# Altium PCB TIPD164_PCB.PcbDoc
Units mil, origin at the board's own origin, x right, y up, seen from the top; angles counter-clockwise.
Board outline 3000 x 3000 mil, 4 copper layers (Top Layer, Mid-Layer 1, Mid-Layer 2, Bottom Layer); 85 components, 50 nets, 262 pads, 186 vias.
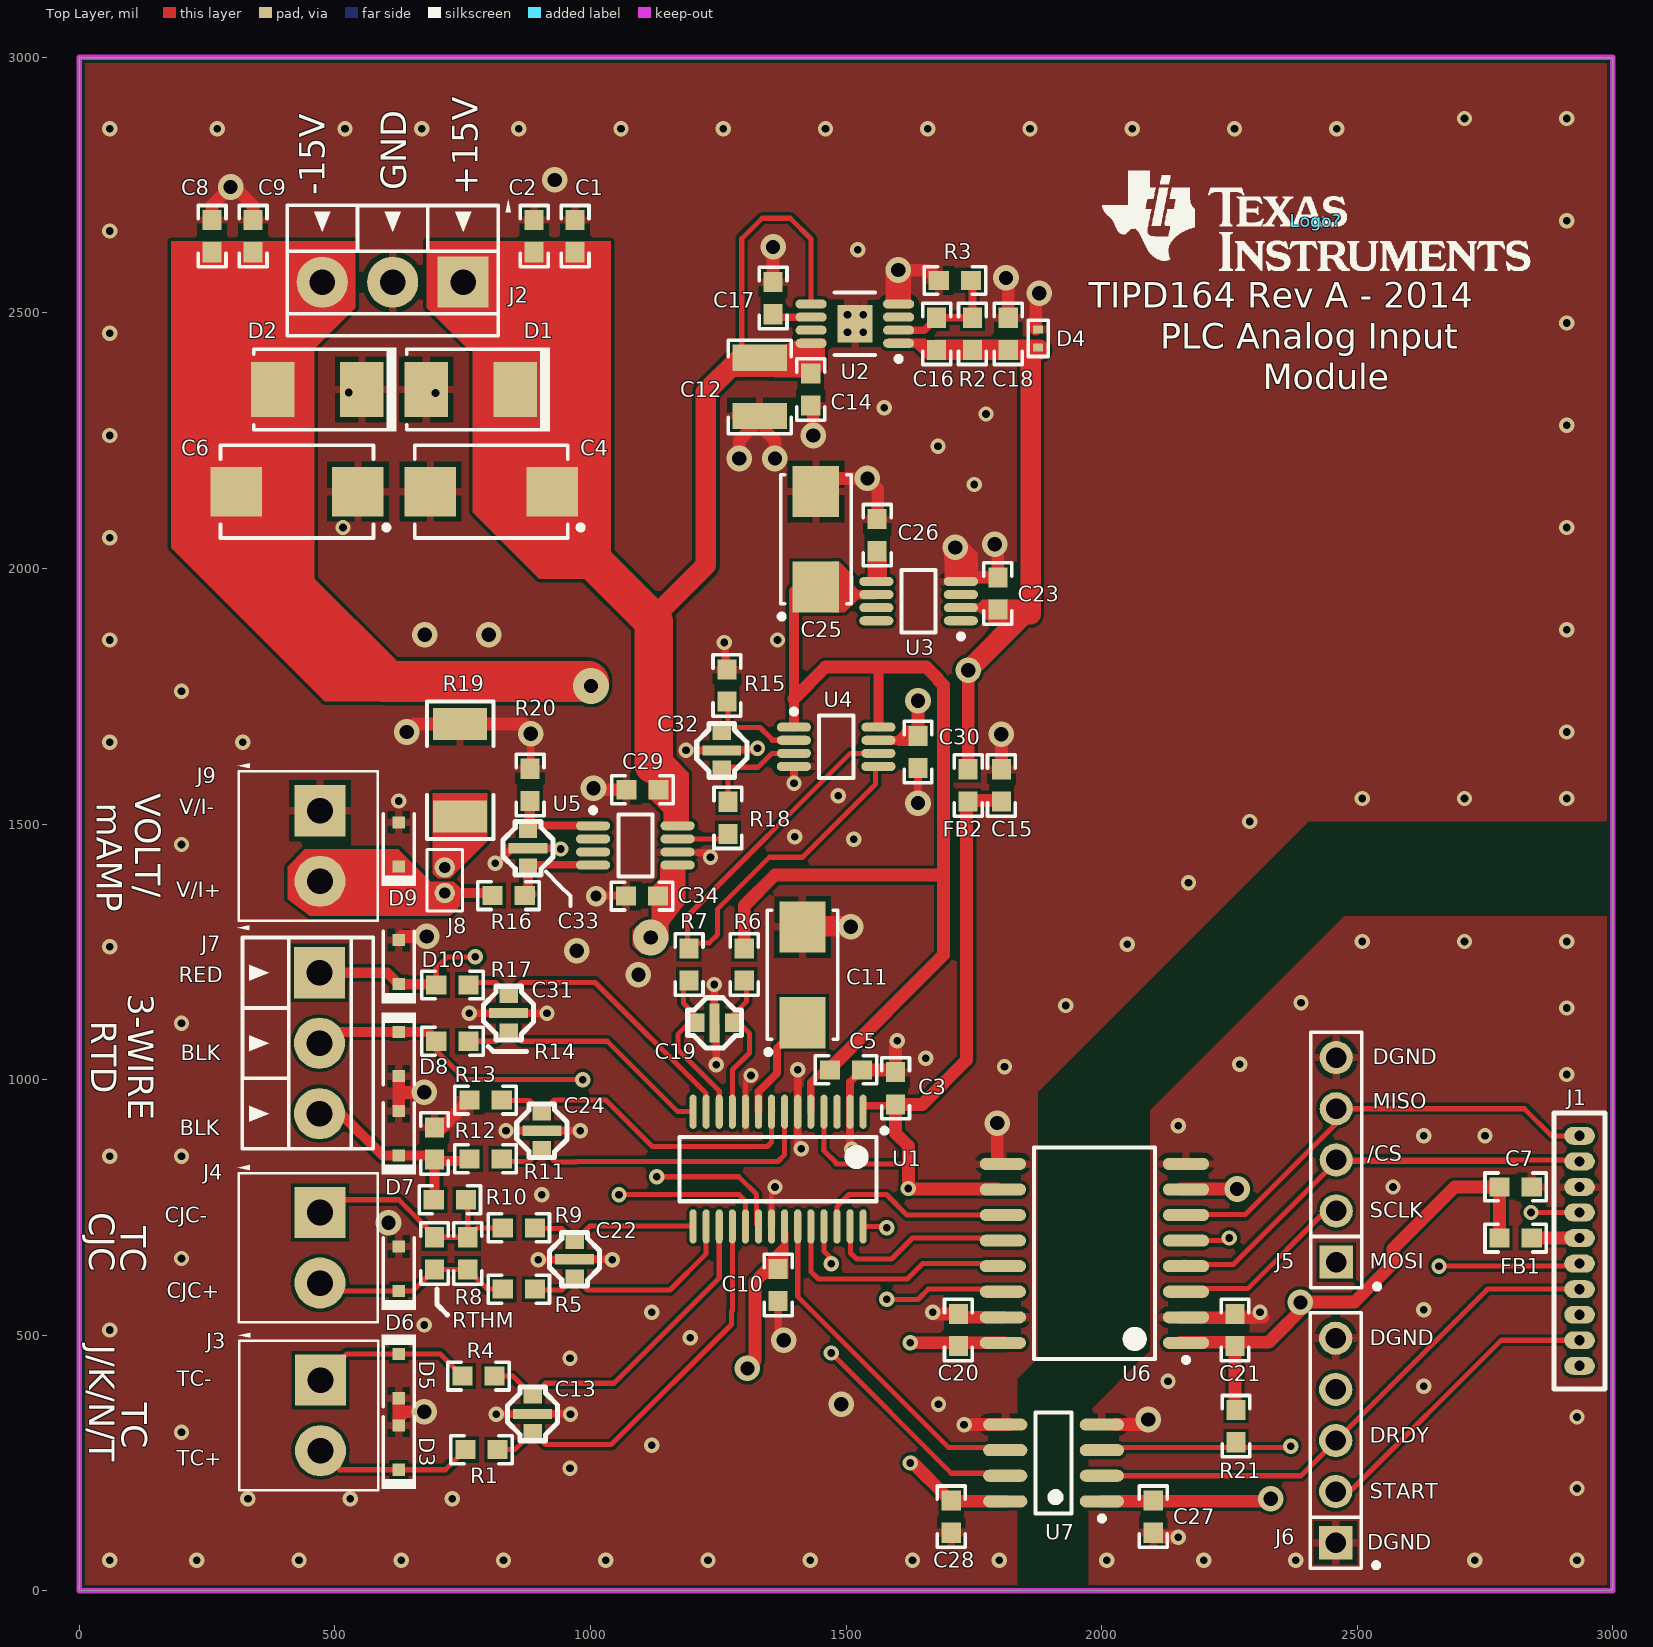
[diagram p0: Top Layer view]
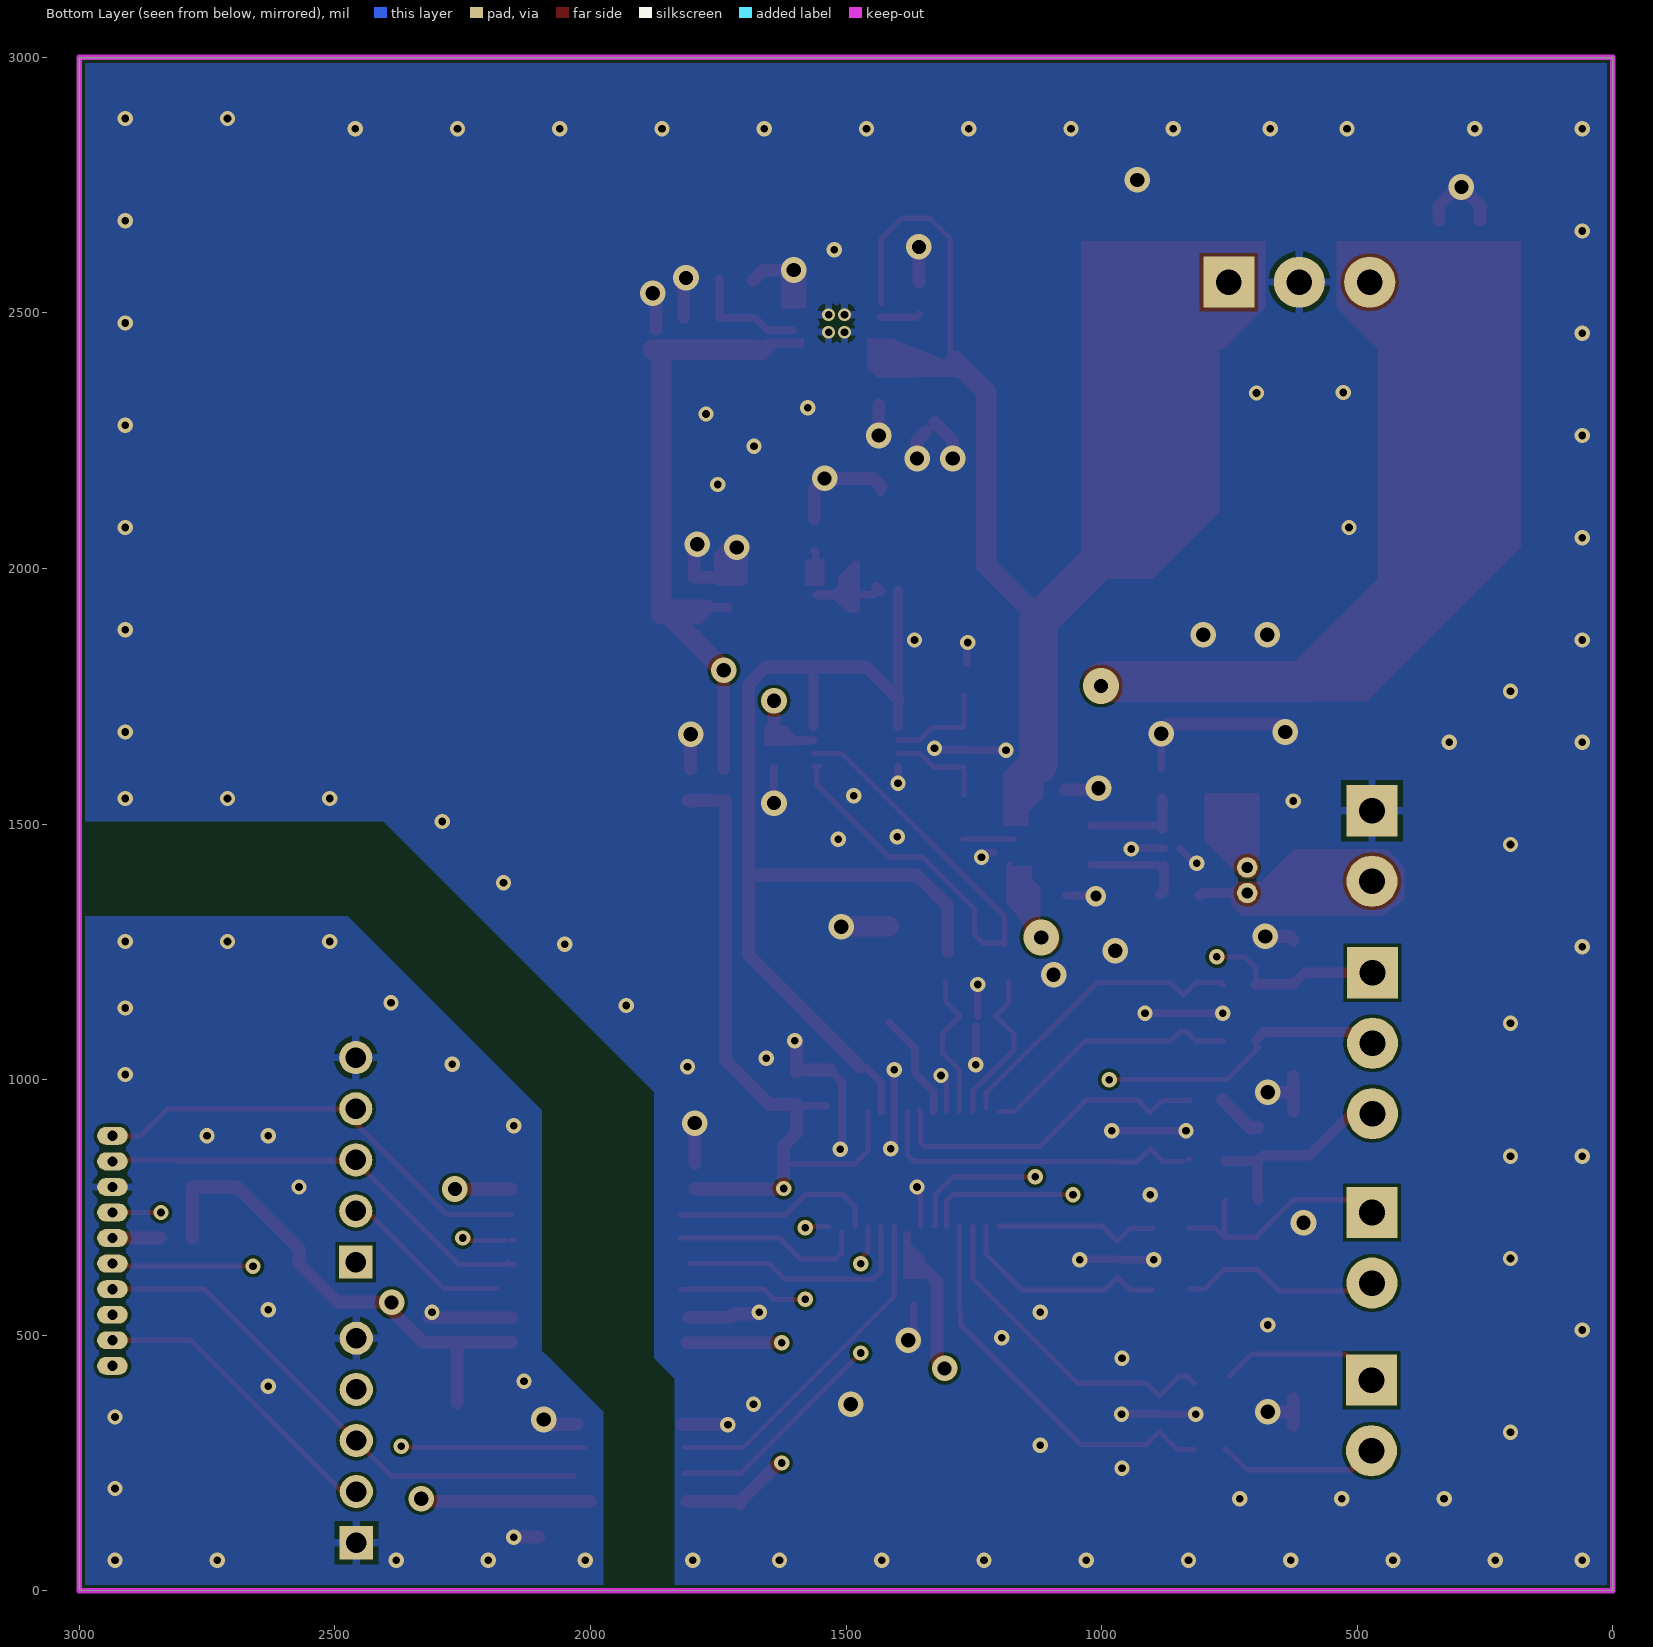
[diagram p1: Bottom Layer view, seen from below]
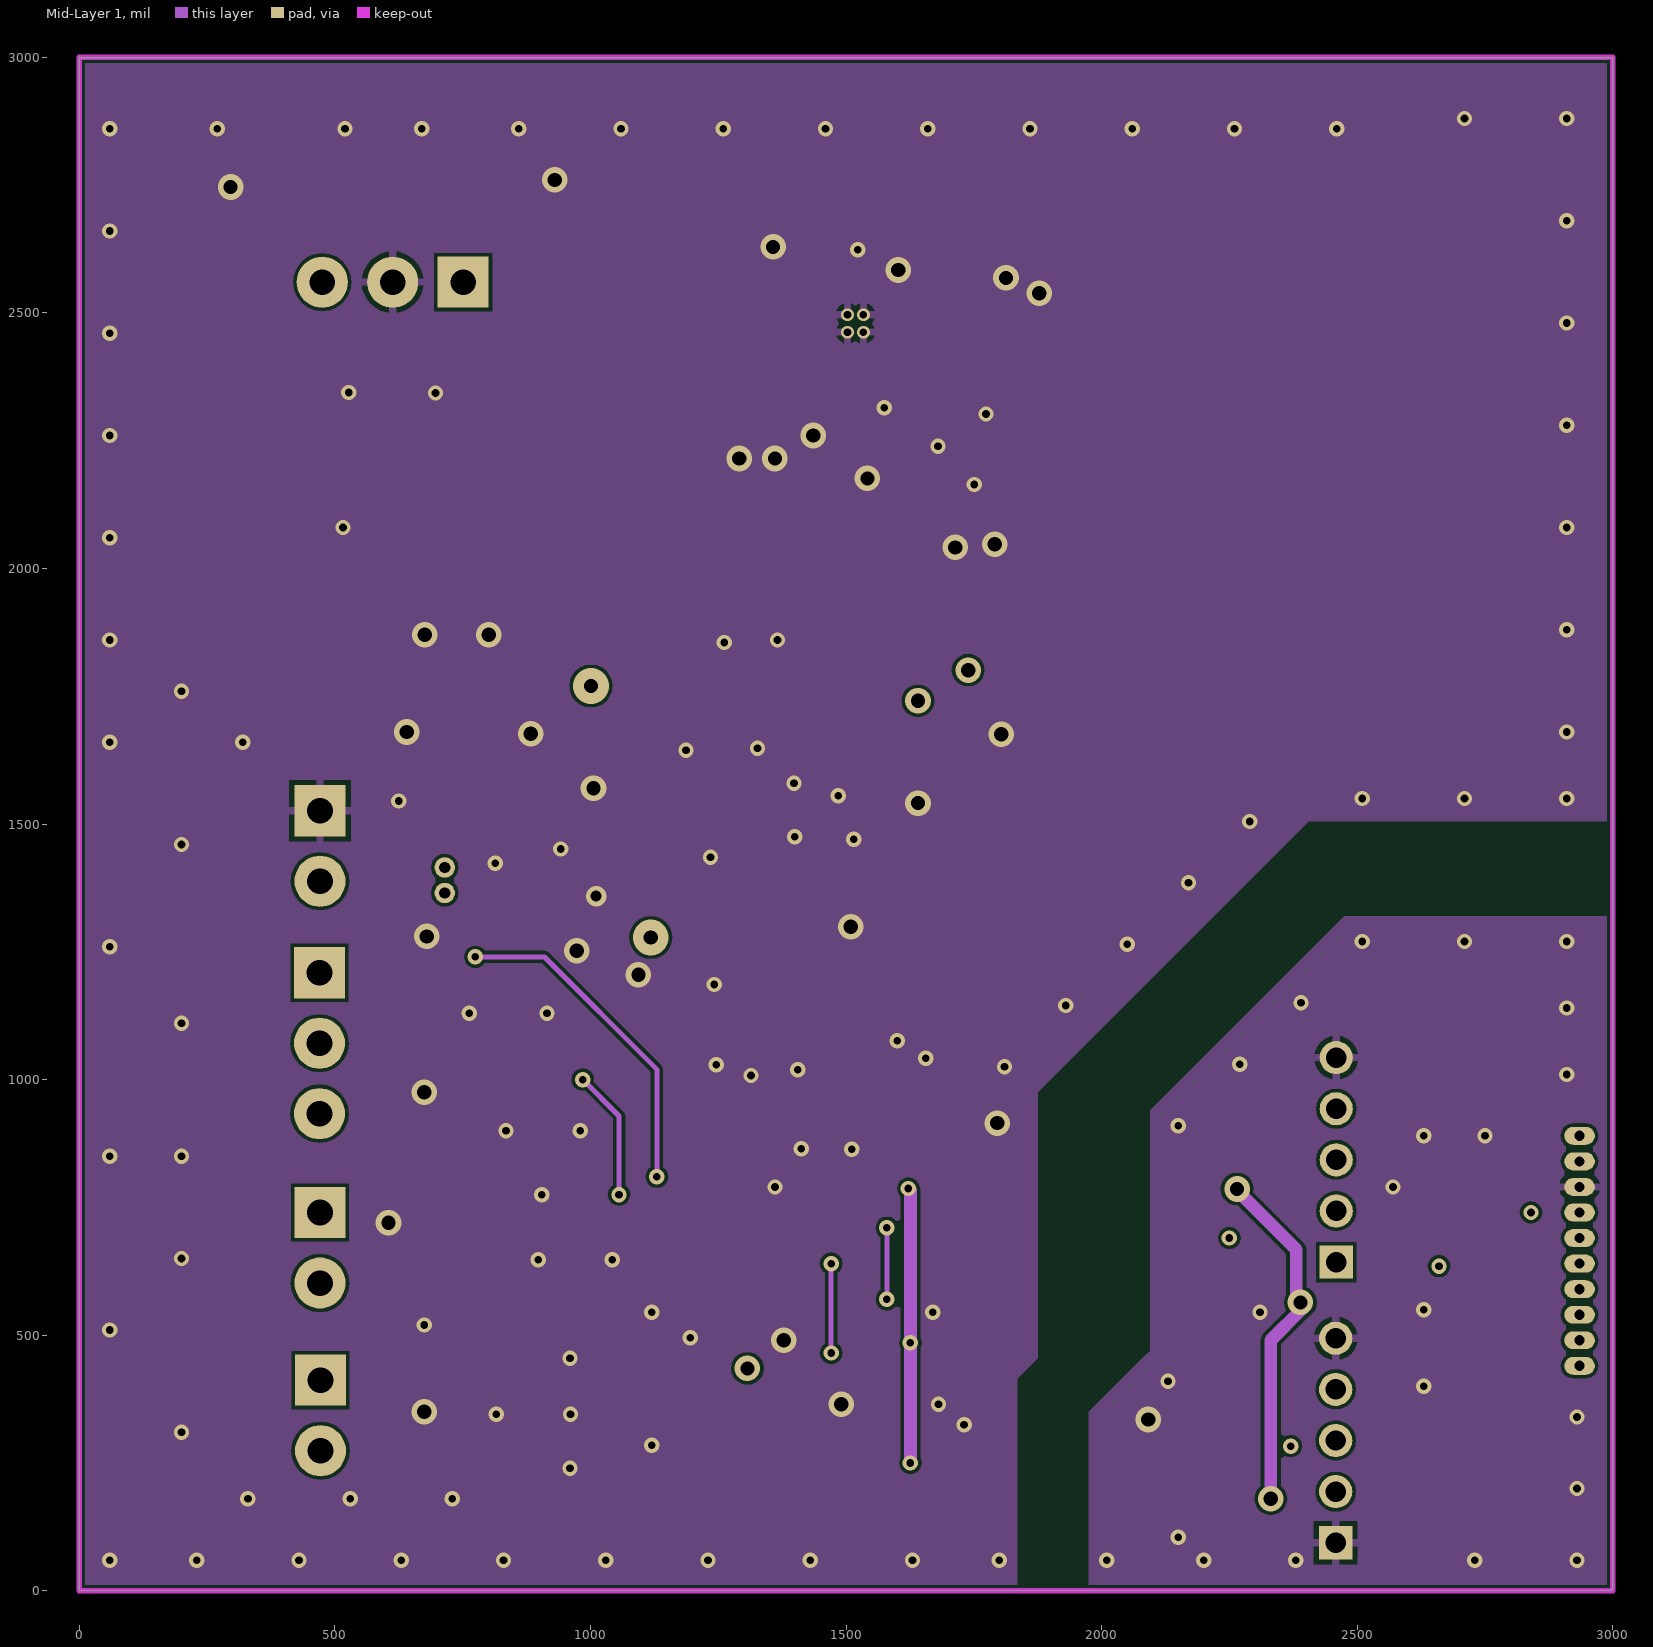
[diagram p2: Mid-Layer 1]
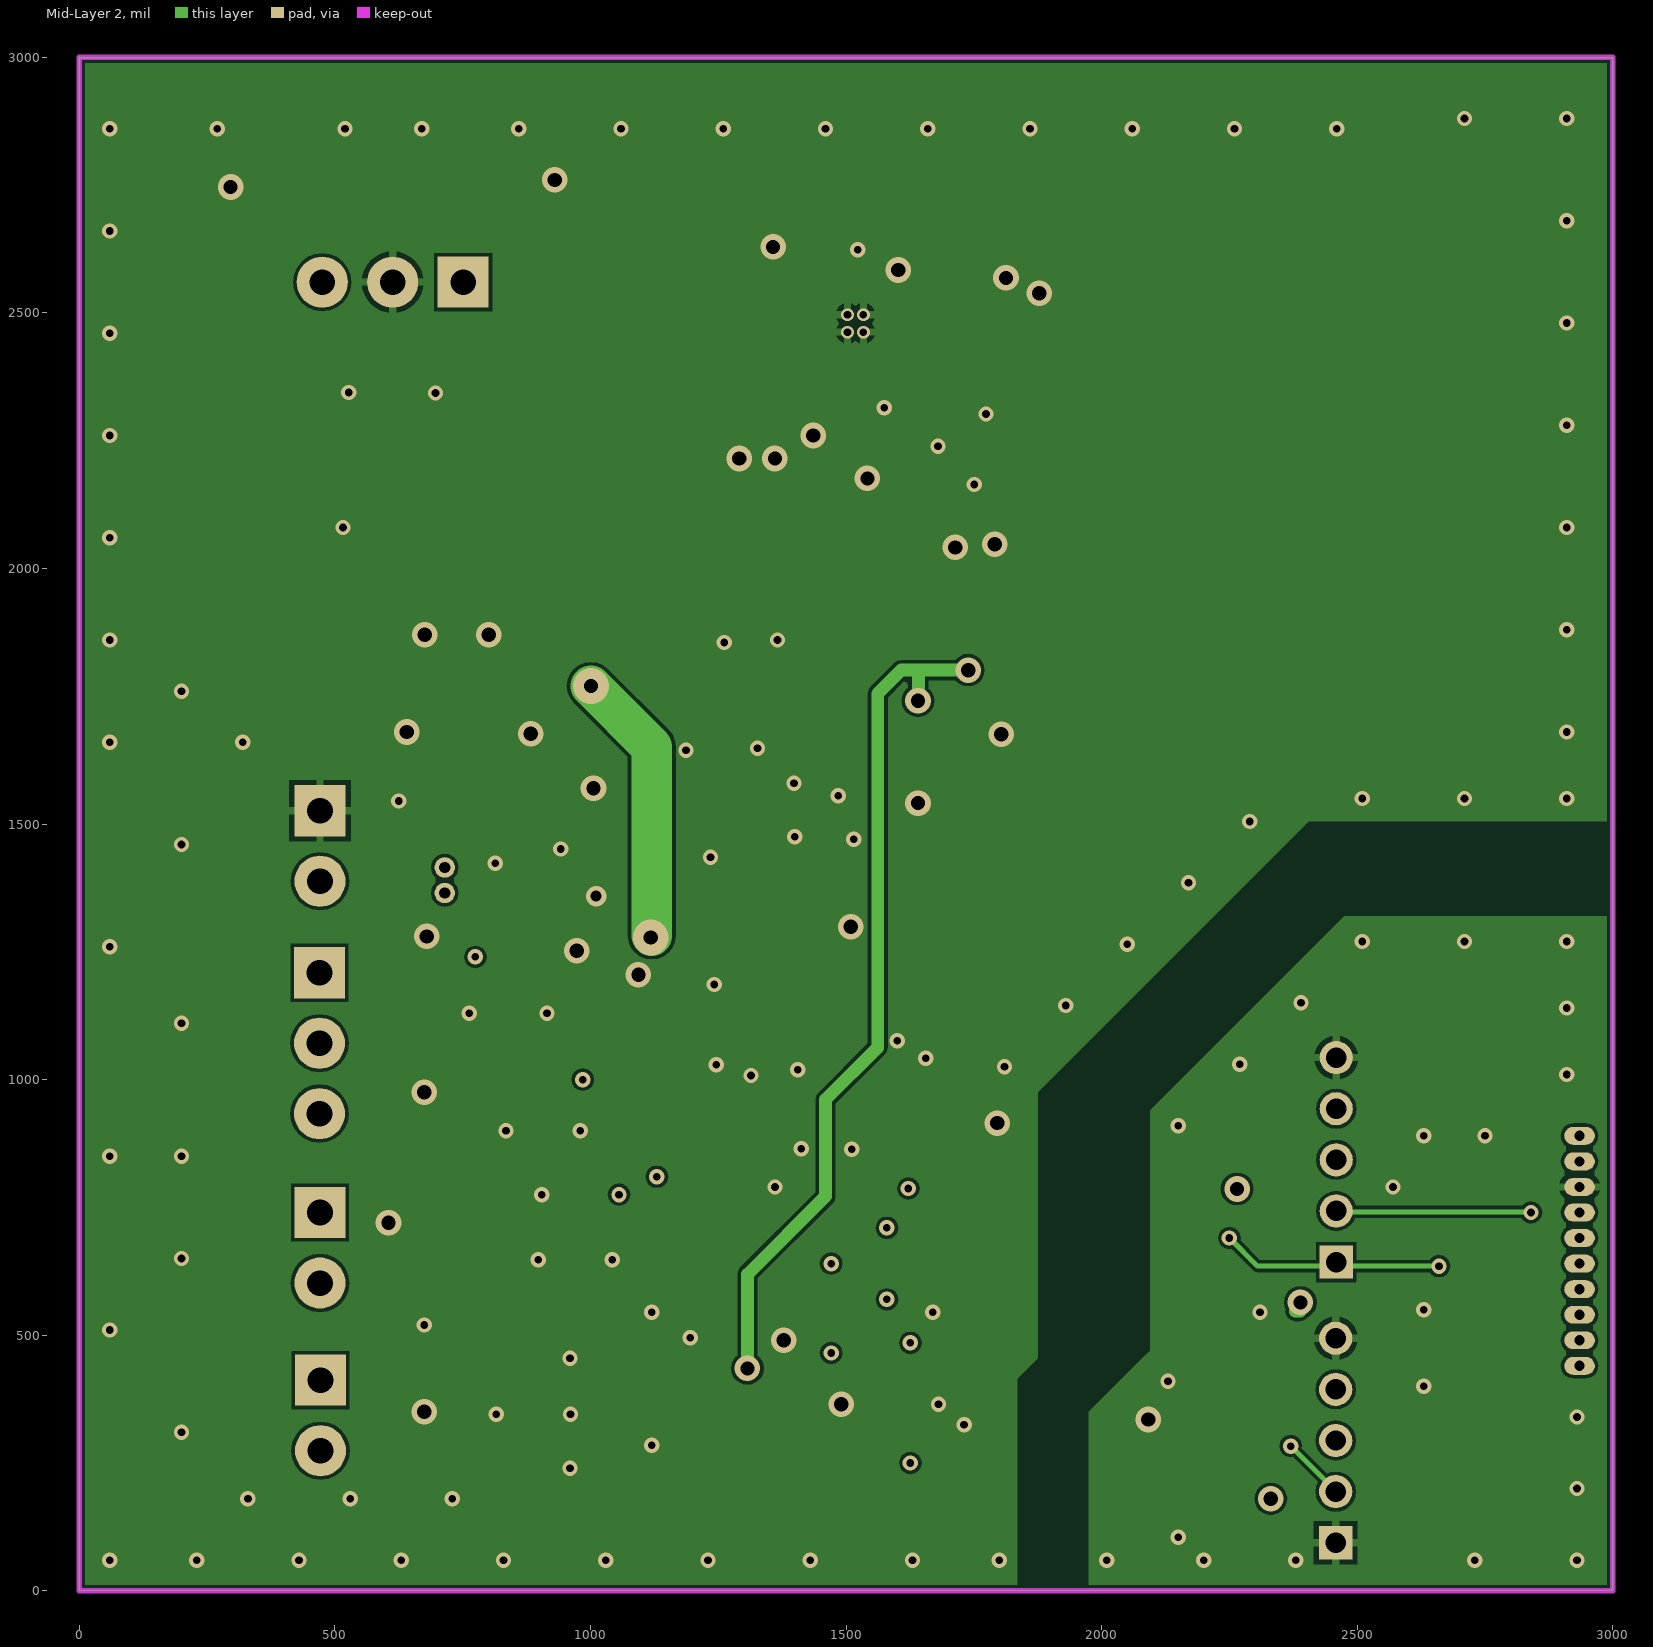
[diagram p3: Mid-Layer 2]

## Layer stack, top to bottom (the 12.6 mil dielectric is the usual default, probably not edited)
Top Layer: signal copper 1.4
Dielectric: core 12.6, FR-4, Dk 4.8
Mid-Layer 1: signal copper 1.4
Dielectric: prepreg 12.6, FR-4, Dk 4.8
Mid-Layer 2: signal copper 1.4
Dielectric: core 12.6, FR-4, Dk 4.8
Bottom Layer: signal copper 1.4

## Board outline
2997,1 3000,4 3000,2999 1,2999 0,3000 0,0

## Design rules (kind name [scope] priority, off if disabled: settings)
Clearance [All] p1: gap=6.5
HoleToHoleClearance [All] p1: gap=0 allowstackedmicrovias=TRUE
MinimumSolderMaskSliver [All] p1: minsoldermaskwidth=0
PolygonConnect PolygonConnect_1 [(InComponentClass('All Components'))] p1: connectstyle=Relief reliefconductorwidth=15 reliefentries=4 polygonreliefangle="90 Angle" airgapwidth=10
PolygonConnect [All] p2: connectstyle=Direct reliefconductorwidth=20 reliefentries=4 polygonreliefangle="90 Angle" airgapwidth=10
RoutingVias [All] p1: holewidth=15 width=30 viastyle="Through Hole" minholewidth=15 minwidth=30 maxholewidth=28 maxwidth=50
SilkToSilkClearance [All] p1 off: silktosilkclearance=10
SilkscreenOverComponentPads [All] p1 off: minsilkscreentomaskgap=10
SolderMaskExpansion [All] p1: expansion=4
Width [All] p1: maxlimit=200 minlimit=10 preferedwidth=10
24 further rules are at their usual default settings.

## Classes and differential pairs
component class Header: J5 J6
component class Logo: Logo?

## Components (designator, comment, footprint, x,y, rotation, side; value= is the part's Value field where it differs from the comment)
C1 "GRM188R71H104KA93D" 0603 970,2650 r270 top
C2 "06035A101JAT2A" 0603 890,2650 r90 top
C3 "GRM188R71H104KA93D" 0603 1597,983 r90 top
C4 "293D106X9050E2TE3" 7343-43 806,2150 r180 top
C5 "GRM188R71H104KA93D" 0603 1500,1019 r0 top
C6 "293D106X9050E2TE3" 7343-43 426,2150 r180 top
C7 "GRM188R71H104KA93D" 0603 2810,790 r0 top
C8 "GRM188R71H104KA93D" 0603 260,2650 r90 top
C9 "06035A101JAT2A" 0603 340,2650 r270 top
C10 "GRM188R71H104KA93D" 0603 1367.2,598 r270 top
C11 "293D226X9010C2TE3" 6032-28 1415,1205 r90 top
C12 "C3225X7R1E106M" 1210 1331,2355 r270 top
C13 "0.047uF X2Y" X2Y_0603 887,346 r90 top
C14 "GRM188R71H104KA93D" 0603 1431,2350 r270 top
C15 "GRM188R71H104KA93D" 0603 1804,1575.5 r90 top
C16 "C0603C103J5RACTU" 0603 1677.37,2458.81 r90 top
C17 "C0603C103J5RACTU" 0603 1357.37,2528.81 r90 top
C18 "GRM188R71H104KA93D" 0603 1817.37,2458.81 r90 top
C19 "0.047uF X2Y" X2Y_0603 1243,1111 r0 top
C20 "GRM188R71H104KA93D" 0603 1720,510 r90 top
C21 "GRM188R71H104KA93D" 0603 2261,510 r90 top
C22 "0.047uF X2Y" X2Y_0603 969,648.5 r90 top
C23 "GRM188R71H104KA93D" 0603 1797,1951 r90 top
C24 "0.047uF X2Y" X2Y_0603 905,900 r90 top
C25 "293D226X9010C2TE3" 6032-28 1441,2057 r90 top
C26 "GRM188R71H104KA93D" 0603 1561,2065 r90 top
C27 "GRM188R71H104KA93D" 0603 2101,145 r270 top
C28 "GRM188R71H104KA93D" 0603 1706,145 r270 top
C29 "GRM188R71H104KA93D" 0603 1102,1567 r180 top
C30 "GRM188R71H104KA93D" 0603 1640.8,1641 r270 top
C31 "0.047uF X2Y" X2Y_0603 840,1130 r90 top
C32 "0.047uF X2Y" X2Y_0603 1257,1644 r270 top
C33 "0.047uF X2Y" X2Y_0603 878,1452.5 r90 top
C34 "GRM188R71H104KA93D" 0603 1101,1359 r180 top
D1 "SMBJ15A-13-F" SMB 766,2350 r180 top
D2 "SMBJ15A-13-F" SMB 466,2350 r180 top
D3 "DESD5V0S1BA" SOD-323 625,280 r90 top
D4 "ESD9L5.0ST5G" SOD-923 1876,2450 r270 top
D5 "DESD5V0S1BA" SOD-323 625,420 r270 top
D6 "DESD5V0S1BA" SOD-323 625,630 r90 top
D7 "DESD5V0S1BA" SOD-323 625,895 r90 top
D8 "DESD5V0S1BA" SOD-323 625,1050 r270 top
D9 "CDSOD323-T15SC" sod-323 625,1460 r90 top
D10 "DESD5V0S1BA" SOD-323 625,1230 r90 top
FB1 "BLM18HG601SN1D" 0603 2810,690 r180 top
FB2 "BLM18HG601SN1D" 0603 1739,1575.5 r270 top
J1 "851-43-050-20-001000" 851-43-010-20-001000 2935,665 r180 top
J2 "ED555/3DS" TERM_BLK_ED555-3DS 751,2560 r180 top
J3 "ED555/2DS" TERM_BLK_ED555-2DS 472,412 r270 top
J4 "ED555/2DS" TERM_BLK_ED555-2DS 471,740 r270 top
J5 "TSW-105-07-G-S" TSW-105-07-G-S 2459,843 r90 top
J6 "TSW-105-07-G-S" TSW-105-07-G-S 2458,294 r90 top
J7 "ED555/3DS" TERM_BLK_ED555-3DS 470,1209 r270 top
J8 "TMS-102-02-G-S" "50mil Header" 715,1365 r90 top
J9 "ED555/2DS" TERM_BLK_ED555-2DS 471,1526 r270 top
Logo? "Texas Instruments" TI_Stacked_Overlay_Small 2420,2680 r0 top
R1 "CRCW0603249RFKEA" 0603 787,276 r180 top
R2 "ERA-3AEB1653V" 0603 1747.37,2458.81 r90 top
R3 "RG1608P-5112-B-T5" 0603 1713,2563.19 r0 top
R4 "CRCW0603249RFKEA" 0603 781,420 r180 top
R5 "RG1608P-2490-B-T5" 0603 860,590 r180 top
R6 "CRCW0603249RFKEA" 0603 1301,1225 r270 top
R7 "CRCW0603249RFKEA" 0603 1193,1225 r270 top
R8 "RG1608P-202-B-T5" 0603 760,660 r270 top
R9 "RG1608P-2490-B-T5" 0603 860,710 r180 top
R10 "CRCW06030000Z0EA" 0603 725,765 r0 top
R11 "CRCW0603249RFKEA" 0603 795,845 r180 top
R12 "RG2012V-822-P-T1" 0603 695,875 r90 top
R13 "CRCW0603249RFKEA" 0603 795,960 r180 top
R14 "CRCW0603249RFKEA" 0603 730,1075 r180 top
R15 "MCT06030C1008FP500" 0603 1267,1771 r270 top
R16 "CRCW0603249RFKEA" 0603 840,1360 r0 top
R17 "CRCW0603249RFKEA" 0603 730,1185 r180 top
R18 "MCT06030C1008FP500" 0603 1269,1512 r90 top
R19 "RT2010BKC07249RL" 2010 745,1605 r270 top
R20 "CRCW0603249RFKEA" 0603 882,1576.5 r270 top
R21 "CRCW0603100KFKEA" 0603 2263,322 r90 top
RTHM "NTCS0603E3473FHT" 0603 695,660 r270 top
U1 "ADS1248" MTC28_N 1367.2,825 r270 top
U2 "TPS7A4901" MUY08A_N 1517.37,2478.81 r180 top
U3 "REF5025" MUA08A_N 1642,1936 r180 top
U4 "INA159" MUA08A_N 1480.8,1651 r0 top
U5 "INA826" MUA08A_N 1088,1458 r0 top
U6 "ISO7641FCDW" M16B_N 1986,660 r180 top
U7 "ISO7221BD" D0008A_N 1906,250 r180 top

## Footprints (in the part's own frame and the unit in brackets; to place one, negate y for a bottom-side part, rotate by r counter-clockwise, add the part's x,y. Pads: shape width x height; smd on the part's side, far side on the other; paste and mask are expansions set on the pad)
"50mil Header" [mil]
  round 40 hole 22: 1(0,0) 2(50,0)
  silkscreen extent -35,-35 85,35
0603 [mm] "0603 from SM-752 data"
  rect 1x0.95 smd: 1(-0.8,0) 2(0.8,0)
  silkscreen extent -1.52,-0.69 1.52,0.69, body extent -0.87,-0.47 0.87,0.47, height 0.85
851-43-010-20-001000 [mil] "Female 10 Pin connector for SM-USB-DIG"
  oval 60x35 hole 20: 1(0,225) 2(0,175) 3(0,125) 4(0,75) 5(0,25) 6(0,-25) 7(0,-75) 8(0,-125) 9(0,-175) 10(0,-225)
  silkscreen extent -50,-270 50,270, body extent -210,-257 8,257, height 87
1210 [mm] "1210 from SM-752 data"
  rect 1.3x2.7 smd: 1(-1.45,0) 2(1.45,0)
  silkscreen extent -2.32,-1.57 2.32,1.57, body extent -1.7,-1.35 1.7,1.35, height 1.35
2010 [mm] "Chip Capacitor, Body 5.08x2.54mm, IPC Medium Density"
  rect 1.6x2.7 smd: 1(-2.3,0) 2(2.3,0)
  silkscreen extent -3.42,-1.65 3.42,1.65, body extent -2.73,-1.45 2.73,1.45, height 1.66
6032-28 [mm] "Medium Density IPC based on Vishay Sprague 293D datasheet."
  rect 2.55x2.3 smd: 1(-2.375,0) 2(2.375,0)
  silkscreen extent -3.96,-1.75 3.2,1.82, body extent -3.15,-1.75 3.15,1.75, height 2.8
7343-43 [mm] "Medium density IPC based on Kemet T495 series"
  rect 2.55x2.45 smd: 1(-3.025,0) 2(3.025,0)
  silkscreen extent -4.56,-2.3 3.8,2.3, body extent -3.8,-2.3 3.8,2.3, height 4.3
D0008A_N [mm] "SOIC, 8-Leads, Body 4.9x3.9mm, Pitch 1.27mm, IPC Medium Density"
  oval 2.2x0.6 smd: 1(-2.4,1.905) 2(-2.4,0.635) 3(-2.4,-0.635) 4(-2.4,-1.905) 5(2.4,-1.905) 6(2.4,-0.635) 7(2.4,0.635) 8(2.4,1.905)
  silkscreen extent -2.53,-2.5 0.9,2.88, body extent -2,-2.5 2,2.5, height 1.75
M16B_N [mm] "SOIC, 16-Leads, Body 10.3x7.5mm, Pitch 1.27mm, IPC Medium Density"
  oval 2.3x0.6 smd: 1(-4.55,4.445) 2(-4.55,3.175) 3(-4.55,1.905) 4(-4.55,0.635) 5(-4.55,-0.635) 6(-4.55,-1.905) 7(-4.55,-3.175) 8(-4.55,-4.445) 9(4.55,-4.445) 10(4.55,-3.175) 11(4.55,-1.905) 12(4.55,-0.635) 13(4.55,0.635) 14(4.55,1.905) 15(4.55,3.175) 16(4.55,4.445)
  silkscreen extent -4.67,-5.25 3,5.42, body extent -3.75,-5.25 3.75,5.25, height 2.65
MTC28_N [mm] "TSOP, 28-Leads, Body 9.7x4.4mm, Pitch 0.65mm, IPC Medium Density"
  oval 1.7x0.35 smd: 1(-2.85,4.225) 2(-2.85,3.575) 3(-2.85,2.925) 4(-2.85,2.275) 5(-2.85,1.625) 6(-2.85,0.975) 7(-2.85,0.325) 8(-2.85,-0.325) 9(-2.85,-0.975) 10(-2.85,-1.625) 11(-2.85,-2.275) 12(-2.85,-2.925) 13(-2.85,-3.575) 14(-2.85,-4.225) 15(2.85,-4.225) 16(2.85,-3.575) 17(2.85,-2.925) 18(2.85,-2.275) 19(2.85,-1.625) 20(2.85,-0.975) 21(2.85,-0.325) 22(2.85,0.325) 23(2.85,0.975) 24(2.85,1.625) 25(2.85,2.275) 26(2.85,2.925) 27(2.85,3.575) 28(2.85,4.225)
  silkscreen extent -2.03,-4.9 1.6,5.41, body extent -2.25,-4.9 2.25,4.9, height 1.1
MUA08A_N [mm] "TSOP, 8-Leads, Body 3x3mm, Pitch 0.65mm, IPC Medium Density"
  oval 1.7x0.45 smd: 1(-2.1,0.975) 2(-2.1,0.325) 3(-2.1,-0.325) 4(-2.1,-0.975) 5(2.1,-0.975) 6(2.1,-0.325) 7(2.1,0.325) 8(2.1,0.975)
  silkscreen extent -2.22,-1.55 0.85,1.87, body extent -1.6,-1.6 1.6,1.6, height 1.09
MUY08A_N [mm] "TSOP, 8-Leads, Body 3x3mm, Pitch 0.65mm, Exposed Pad, IPC Medium Density"
  oval 1.55x0.45 smd: 1(-2.175,0.975) 2(-2.175,0.325) 3(-2.175,-0.325) 4(-2.175,-0.975) 5(2.175,-0.975) 6(2.175,-0.325) 7(2.175,0.325) 8(2.175,0.975)
  rect 1.73x1.85 smd: 9(0,0)
  silkscreen extent -2.3,-1.55 1,1.87, body extent -1.55,-1.55 1.55,1.55, height 1.09
SMB [mil] "Molded Diode, 2-Leads, Body 5.4x3.6mm, IPC Medium Density, based on OnSemi component dimensions"
  rect 85x107.99 smd: 1(-87.01,0) 2(87.01,0)
  silkscreen extent -155,-82 125,82, body extent -106,-71 106,71, height 91
SOD-323 [mm] "NXP recommended land pattern"
  rect 0.6x0.6 smd paste-0.05: 1(-1.1,0) 2(1.1,0)
  silkscreen extent -2.06,-0.86 1.53,0.86, body extent -1.3,-0.67 1.3,0.68, height 1.1
sod-323 [mm] "NXP recommended land pattern"
  rect 0.6x0.6 smd paste-0.05: 1(-1.1,0) 2(1.1,0)
  silkscreen extent -2.06,-0.86 1.53,0.86, body extent -1.3,-0.67 1.3,0.68, height 1.1
SOD-923 [mm]
  rect 0.4x0.5 smd: 1(-0.45,0) 2(0.45,0)
  silkscreen extent -0.9,-0.5 0.9,0.5
TERM_BLK_ED555-2DS [mil]
  rect 100x100 hole 50: 1(0,0)
  round 100 hole 50: 2(138,0)
  silkscreen extent -93,-161 215,113, body extent -69,-150 207,106, height 323
TERM_BLK_ED555-3DS [mm]
  rect 2.54x2.54 hole 1.27: 1(0,0)
  round 2.54 hole 1.27: 2(3.5,0) 3(7,0)
  silkscreen extent -2.36,-4.09 8.75,2.67, body extent -1.75,-3.83 8.75,2.67, height 8.2
TI_Stacked_Overlay_Small [mil]
  silkscreen extent -418,-98 418,98
TSW-105-07-G-S [mm] "Samtec 100mil, 1x5, 230 mil above insulator"
  rect 1.65x1.65 hole 1.016 mask+0: 1(-5.08,0)
  round 1.65 hole 1.016 mask+0: 2(-2.54,0) 3(0,0) 4(2.54,0) 5(5.08,0)
  silkscreen extent -6.42,-2.16 6.35,1.27, body extent -6.35,-1.27 6.35,1.27, height 8.38
X2Y_0603 [mil]
  rect 30x36 smd: 1(-35,0) 2(35,0)
  rect 20x76 smd: 3(0,0)
  silkscreen extent -52,-49 52,49

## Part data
C1 C3 C5 C7 C8 C10 C14 C15 C18 C20 C21 C23 C26 C27 C28 C29 C30 C34: "CAP, CERM, 0.1uF, 50V, +/-10%, X7R, 0603"
C2 C9: "CAP, CERM, 100pF, 50V, +/-5%, C0G/NP0, 0603"
C4 C6: "CAP, TANT, 10uF, 50V, +/-10%, 0.8 ohm, 7343-43 SMD"
C11 C25: "CAP, TANT, 22uF, 10V, +/-10%, 1.5 ohm, 6032-28 SMD"
C12: "CAP, CERM, 10uF, 25V, +/-20%, X7R, 1210"
C13 C19 C22 C24 C31 C32 C33: library part "X2Y Capacitor", "CAP CER 0.047UF 16V 20% X7R 0603"
C16 C17: "CAP, CERM, 0.01uF, 50V, +/-5%, X7R, 0603"
D1 D2: "Diode, TVS, Uni, 15V, 600W, SMB"
D3 D5 D6 D7 D8 D10: library part SMAJ15CA, "DIODE TVS 5.0V 130W"
D4: library part SMAJ15CA, "TVS ESD PROT ULT LOW CAP SOD-923"
D9: library part SMAJ15CA, "DIODE TVS ARRAY 15V SOD323"
FB1 FB2: library part Ferrite_Bead, "FERRITE CHIP 600 OHM 200MA 0603"
J1: library part SM-USB-DIG-CONN, "CONN SOCKET 50PIN .050 R/A SNGL"
J2 J7: "Terminal Block, 6A, 3.5mm Pitch, 3-Pos, TH"
J3 J4 J9: "Terminal Block, 6A, 3.5mm Pitch, 2-Pos, TH"
J5 J6: "Header, TH, 100mil, 5x1, Gold plated, 230 mil above insulator"
J8: library part Shunt, "CONN HEADER 2POS .050\" T/H GOLD"
Logo?: library part TI_Logo, "Texas Instrument Corporate Signature"
R1 R4 R6 R7 R11 R13 R14 R16 R17 R20: "RES, 249 ohm, 1%, 0.1W, 0603"
R2: library part RT0603BRD07164KL, "RES 165K OHM 1/10W .1% 0603 SMD"
R3: "RES, 51.1k ohm, 0.1%, 0.1W, 0603"
R5 R9: library part CRCW0603249RFKEA, "RES 249 OHM 1/10W .1% 0603 SMD"
R8: "RES, 2.00k ohm, 0.1%, 0.1W, 0603"
R10: "RES, 0 ohm, 5%, 0.1W, 0603"
R12: library part RC0603FR-078K2L, "RES 8.2k OHM 1/16W .02% 0805"
R15 R18: library part CRCW06031R00FKEA, "RES 1.00 OHM 1/8W 1% SMD 0603"
R19: library part CRCW1206249RFKEA, "RES 249 OHM 1/2W .1% 2010 SMD"
R21: "RES, 100k ohm, 1%, 0.1W, 0603"
RTHM: library part CRCW0603100KJNEA, "THERMISTOR NTC 47K 1% 0603"
U1: "IC ADC 24BIT DEL/SIG LN 28TSSOP"
U2: "IC REG LDO ADJ .15A 8MSOP"
U3: "IC VREF SERIES PREC 2.5V 8-MSOP"
U4: "IC OPAMP DIFF 1.5MHZ SGL 8MSOP"
U5: "IC OPAMP INSTR 1MHZ 8MSOP"
U6: library part ISO7241, "ISOLATOR DGTL 25MBPS 4CH 16SOIC"
U7: "5 Mbps Dual Channels, 1 / 1, Digital Isolator, 3.3 V / 5 V, -40 to +125 degC, 8-pin SOIC (D), Green (RoHS & no Sb/Br)"

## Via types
v1: diameter 30, hole 15, Top Layer to Bottom Layer, 143 vias
v2: diameter 50, hole 28, Top Layer to Bottom Layer, 36 vias
v3: diameter 25, hole 15, Top Layer to Bottom Layer, 4 vias
v4: diameter 70, hole 28, Top Layer to Bottom Layer, 2 vias
v5: diameter 40, hole 22, Top Layer to Bottom Layer, 1 vias

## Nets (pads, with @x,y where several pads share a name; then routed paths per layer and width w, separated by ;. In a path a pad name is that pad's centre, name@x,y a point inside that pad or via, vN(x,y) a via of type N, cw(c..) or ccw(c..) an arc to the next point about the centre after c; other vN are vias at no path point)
+2.5VA: C5.1 C25.1 R6.1 U1.5 U3.6 U4.1 U4.8 | length 2280.4
  Top Layer w15: U1.5 1431.18,994.48 C5.1@1460,1023.3 ; C25.1@1445.7,1948.8 U3.6
  Top Layer w20: U4.1@1398.12,1691.15 1398.12,1745 C25.1@1398.12,1955.61 ; C25.1@1433.12,1955.61 C25.1 ; U4.8@1563.47,1691.15 1563.47,1807
  Top Layer w25: R6.1@1301,1250 1301,1340 1361,1400 1691,1400 ; 1398.12,1745 1460.12,1807 1563.47,1807 1657,1807 1679.5,1784.5 1679.5,1782.98 1691,1771.48 1691,1400 ; C5.1@1471,1024.3 1691,1244.3 1691,1400
+5VA: C10.1 C16.1 C18.1 C23.1 C30.1 D4.2 FB2.1 R2.1 U1.22 U2.1 U3.2 U4.7 | length 3215.6
  Top Layer w15: U4.7 1632.09,1663.8 C30.1
  Top Layer w25: v2(1307.2,435) 1322.2,450 1322.2,605 1344.2,627 C10.1@1372.71,627 ; C30.1 v2(1640.8,1741) ; FB2.1@1739,1608 v2(1739,1801) ; C23.1@1797,1922 1858,1922
  Top Layer w40: C16.1 R2.1 C18.1 D4.2@1877.92,2427.32 ; v2(1739,1801) 1859,1921 ; 1861,1910 1861,2425
  Mid-Layer 2 w25: v2(1307.2,435) 1307.2,619 1460,771.8 1460,961 1562,1063 1562,1755 1608,1801 v2(1739,1801) ; v2(1640.8,1741) 1642,1742.2 1642,1799 ; v2@1739,1799 v2@1750,1799
+15VA: C1.2 C2.1 C4.1 C12.1 C14.1 C29.1 D1.1 J2.1 U2.5 U2.8 U5.8 | length 1665.7
  Top Layer w10: C29.1@1148.5,1560 1179.68,1528.82 ; 1179.68,1518.39 1179.68,1548.82 ; C12.1@1286,2405 1296,2415 1296,2645 1336,2685 1391,2685 1431.74,2644.26 U2.5 ; C12.1@1320.19,2388.81 C12.1@1344.46,2388.81
  Top Layer w40: 1136,1916 1226,2006 1226,2345 C12.1@1286,2405
  Top Layer w75: 1000,2040 1000,2020 1124,1896 1124,1616
-15VA: C6.2 C8.1 C9.2 C34.1 D2.2 J2.3 U5.5 | length 1125.3
  Top Layer w10: v4@1123,1296 1148.5,1321.5 1148.5,1360 1158.5,1360 1179.68,1381.18 U5.5@1179.68,1421.61
  Top Layer w50: J2.3@454.42,2576.68 J2.3@477.09,2554
  Top Layer w80: 595,1779 v4@996,1779
  Mid-Layer 2 w80: v4(1001,1770) 1120,1651 v4@1120,1282
  other v4: 1118,1278
\C\S_DIG: J1.9 J5.3 U6.4 | length 1238.7
  Top Layer w10: U6.4@2146.63,638.5 2257.5,638.5 2459,840 2808,840 ; U6.4@2148.13,636 2154.13,636 U6.4@2161.63,643.5 ; J5.3 2932,843 J1.9
C\S\_AI: U1.24 U6.13 | length 481.4
  Top Layer w10: U1.24 1431.18,624.82 1446,610 1620,610 1650,640 U6.13@1806,640
DGND: C7.2 C21.2 C27.2 J1.8 J5.5 J6.1 J6.5 U6.2 U6.8 U7.4 | length 279.3
  Top Layer w25: U7.4@2026,325 v2@2081,325 ; C27.2@2101,105 v1(2150,105) ; U6.2@2153.63,534 2297,534 2298,535 2316,535 2310,541 v1(2310,545)
  other v1: 2010,60 2200,60 2380,60 2730,60 2930,60 2930,200 2930,340 2630,400 2130,410 2630,550 2570,790 2630,890 2750,890 2150,910 2910,1010 2270,1030 2910,1140 2390,1150 2510,1270 2710,1270 2910,1270
  other v2: 2091,335
DRDY: U1.25 U7.7 | length 696.5
  Top Layer w10: U1.25 1456.77,664.23 1471,650 v1(1471,640) ; v1(1471,465) 1706,230 U7.7@1816.51,230
  Mid-Layer 1 w10: v1(1471,465) v1(1471,640)
DRDY_DIG: J1.4 J6.3 U7.2 | length 1055.2
  Top Layer w10: U7.2@2031,225 2390,225 2755,590 J1.4
DVDD_A: C3.1 C15.1 C20.1 C28.1 FB2.2 U1.1 U1.4 U6.10 U6.16 U7.8 | length 2376
  Top Layer w10: 1456,862 1483.23,834.77 ; 1456.77,862 U1.4 ; 1481,835 1619,835
  Top Layer w15: U1.1@1540,949 C3.1@1589.32,949
  Top Layer w25: v1(1626,485) U6.16 U6.16@1811,485 ; v1@1628.5,252.5 C28.1@1699.5,181.5 ; C28.1@1707.5,170 1712.5,175 U7.8 ; 1764,1546.5 C15.1@1809,1546.5 ; U6.10@1795.87,786 1623,786 v1(1622,787) 1622,870 1597,895 C3.1 1649,951.5 1736,1038.5 1736,1545.5 1802.5,1545.5 C15.1
  Mid-Layer 1 w25: v1(1622,787) 1626,783 v1(1626,485) v1(1626,250)
GNDA: C1.1 C2.2 C3.2 C4.2 C5.2 C6.1 C8.2 C9.1 C10.2 C11.2 C12.2 C13.3 C14.2 C15.2 C17.2 C18.2 C19.3 C20.2 C22.3 C23.2 C24.3 C25.2 C26.2 C28.2 C29.2 C30.2 C31.3 C32.3 C33.3 C34.2 D1.2 D2.1 D3.2 D4.1 D5.2 D6.2 D7.2 D8.2 D9.2 D10.2 J2.2 J9.1 R3.1 R12.2 R13.2 R15.1 R19.1 R20.1 U1.2 U1.6 U1.10 U1.21 U2.4 U2.9 U3.4 U4.4 U5.6 U6.9 U6.15 U7.5 | length 4169.7
  Top Layer w10: v1@940.5,1452.5 v1(942,1451) ; U1.10 1303.23,997.02 v1(1314.2,1008) ; U1.21 1354.41,782.8 1352.2,785 1357.2,790 v1(1361.2,790)
  Top Layer w15: v1(763,1130) C31.3@838,1130 ; v1@815.5,1421.5 C33.3@846,1452 ; v1(816,345) 886,345 C13.3 960,346 v1(961,345) ; v1(835,900) v1(980,900) ; C31.3 v1(915,1130) ; C33.3 v1@940.5,1452.5 ; R20.1@883,1608 v2(883,1676.5) v2@883,1682.5 ; v1(898,647.5) 968,647.5 C22.3 1042,648.5 v1(1043,647.5) ; v5@1001,1360 C34.2@1069.5,1360 ; v1(1187,1644) C32.3 C32.3@1269,1644 ; 1211,1444 1226,1444 v1(1235,1435) ; C19.3@1242,1124.5 v1(1242,1186) ; v1(1246,1029) C19.3@1246,1104 ; C32.3@1258.5,1645.5 v1@1324.5,1645.5 ; R15.1@1264,1815 v1@1264,1855 ; C10.2@1367.2,558.5 1367.2,490 v2(1378.2,490) ; v1(1398.12,1580) U4.4 ; v1(1405.59,1019) U1.6 1405.59,871.61 v1(1412.2,865) ; C25.2@1432,2149.5 C25.2@1437,2154.5 ; v1(1511.2,864) 1507.95,867.25 U1.2 1507.95,995.46 C5.2 ; v2(1602.37,2583.81) 1603,2583.19 U2.4 ; v2(1640.8,1541) C30.2 ; U3.4 U3.4@1726,1975.71
  Top Layer w25: C8.2 260,2710 300,2750 340,2710 C9.1 ; D3.2 625,339 ; D5.2 625,339 ; D7.2 625,975 ; D8.2 625,975 ; D10.2 631.69,1280 v2(680,1280) ; v2(641,1680) 656.55,1695.55 750,1695.55 869.95,1695.55 v2@883,1682.5 ; v2(675,350) 636,350 625,339 ; v2@680,975 625,975 ; R12.2 710,906.5 R13.2 ; v2@1004,1580 1017,1567 C29.2 ; v2@1291,2227.91 1291,2250 C12.2@1326,2285 ; v1@1324.5,1645.5 v1(1327,1648) ; 1343.09,2267.91 1361,2250 v2(1361,2215) ; C17.2 v2(1357.37,2628.81) ; C25.2@1431,2160.5 1446.5,2176 v2(1542,2176) v2@1552,2166 ; v2@1436,2251.5 C14.2@1436,2320 ; C5.2 C3.2@1580,1019 ; C26.2@1562,2097.5 1562,2156 ; C3.2 v1@1597,1073 ; v2@1603,2583.19 1661.5,2583.19 R3.1 ; v1(1670,545) 1673.5,541.5 C20.2 1726.5,535 U6.15 ; v1(1731,325) U7.5@1821.51,325 ; 1753.5,1982.5 C23.2 1797,2041 v2(1791,2047) ; U6.9@1795.87,836 v2@1795.87,917 ; C15.2 v2(1804,1675.5) ; C18.2 v2@1817.37,2548.81 ; D4.1@1871,2467.72 v2@1871,2525 ; v2@1883,2528.19 v2@1888,2533.19
  Top Layer w40: C11.2@1416.5,1300 1510,1300 v2(1509,1299)
  other v1: 60,60 230,60 430,60 630,60 830,60 1030,60 1230,60 1430,60 1630,60 1800,60 330,180 530,180 730,180 960,240 1120,285 200,310 1681,365 960,455 1195,495 60,510 675,520 1120,545 200,650 905,775 60,850 200,850 1810,1025 1656,1042 1600,1076 200,1110 1930,1145 60,1260 2050,1265 2170,1385 814,1423 200,1460 1515,1470 1400,1475 2290,1505 625,1545 2510,1550 2710,1550 2910,1550 1485,1555 60,1660 320,1660 2910,1680 200,1760 1262,1855 60,1860 1366,1860 2910,1880 60,2060 516,2080 2910,2080 1751,2164 1680,2239 60,2260 2910,2280 1774,2302 1575,2314 697.09,2343 527.09,2344 60,2460 2910,2480 1523,2623.19 60,2660 2910,2680 60,2860 270,2860 520,2860 670,2860 860,2860 1060,2860 1260,2860 1460,2860 1660,2860 1860,2860 2060,2860 2260,2860 2460,2860 2710,2880 2910,2880
  other v2: 1491,365 605,720 1796,915 675,975 1094,1205 973,1252 1006,1570 676,1870 801,1870 1714,2041 1291,2215 1436,2260 1878,2538.19 1813,2568.19 296.09,2746.09 930,2760
  other v3: 1503,2462.19 1534,2462.19 1503,2496.19 1534,2496.19
  other v5: 1011,1359
IEXC1: D10.1 J7.1 R17.2 U1.20 | length 1286.9
  Top Layer w10: R17.2 698.5,1218.5 720,1240 v1(775,1240) ; v1(1130,810) 1290.2,810 1325.2,775 1325.2,716.41 U1.20
  Top Layer w20: J7.1 602.69,1209 D10.1 696.81,1186.69 R17.2
  Mid-Layer 1 w10: v1(775,1240) 910,1240 1130,1020 v1(1130,810)
IEXC2: D8.1 J7.2 R14.2 U1.19 | length 1137.5
  Top Layer w10: R14.2@691.81,1063.19 R14.2@696.81,1058.19 ; R14.2@696.81,1078.31 R14.2@696.81,1058.19 ; v1(985,1000) 755,1000 R14.2@696.81,1058.19 ; v1(1056,775) 1291.2,775 ; 1291.2,774 1303.23,761.98 U1.19
  Top Layer w20: J7.2 492.1,1093.31 D8.1 681.81,1093.31 R14.2@696.81,1078.31
  Mid-Layer 1 w10: v1(985,1000) 1056,929 v1(1056,775)
MISO_DIG: J1.10 J5.4 U6.6 | length 905.5
  Top Layer w10: U6.6@2154.13,736 2281,736 2459,914 J5.4 2827,943 2880,890 J1.10
MOSI_DIG: J1.5 J5.1 U6.5 | length 811.8
  Top Layer w10: U6.5@2148.13,686 U6.5@2154.13,686 ; U6.5 2245,685 v1(2250,690) ; v1@2651,635 2930,635 J1.5
  Mid-Layer 2 w10: v1(2250,690) 2305,635 v1(2660,635)
NetC11_1: C11.1 U1.9 | length 210
  Top Layer w15: U1.9 1328.82,976.61 1365,1012.8 1365,1061.5 C11.1
NetC13_1: C13.1 R1.1 U1.18 | length 772.2
  Top Layer w10: R1.1 852,276 C13.1 912,286 1041,286 1276,521 1276,547 1277.64,548.64 U1.18
NetC13_2: C13.2 R4.1 U1.17 | length 652
  Top Layer w10: R4.1@818.5,406 832.5,420 848,420 C13.2 912,406 1046,406 1252.05,612.05 U1.17
NetC16_2: C16.2 R2.2 R3.2 U2.2 | length 231.4
  Top Layer w15: U2.2 1653.08,2466.02 C16.2 R2.2 R3.2@1747.37,2567.32
NetC17_1: C17.1 U2.6 | length 76.7
  Top Layer w15: C17.1 1363.08,2491.61 U2.6
NetC19_1: C19.1 R7.2 U1.12 | length 313.6
  Top Layer w10: 1171,1087.5 1171,1058.63 1252.05,977.58 U1.12 ; 1171,1088.5 1207,1124.5 1182,1149.5 R7.2@1182,1193.01
NetC19_2: C19.2 R6.2 U1.11 | length 295.3
  Top Layer w10: U1.11 1277.64,1018.64 1311,1052 1311,1090.5 1277,1124.5 1305,1152.5 R6.2@1305,1193
NetC22_1: C22.1 R5.1 U1.16 | length 429.6
  Top Layer w10: R5.1@900.5,588.5 944,588.5 C22.1 994,588.5 1155.46,588.5 ; 1155.46,588.25 1226.46,659.25 U1.16
NetC22_2: C22.2 R9.1 U1.15 | length 323.3
  Top Layer w10: R9.1@900.5,708.5 944,708.5 C22.2 999.29,713.8 U1.15@1200.87,713.8
NetC26_1: C26.1 U3.5 | length 61.2
  Top Layer w15: U3.5 1559.32,2031.83 C26.1@1562,2034.5
NetC31_1: C31.1 R14.1 U1.14 | length 513
  Top Layer w10: R14.1 815,1075 835,1095 C31.1 845,1095 865,1075 1033,1075 1170.8,937.2 U1.14
NetC31_2: C31.2 R17.1 U1.13 | length 605.5
  Top Layer w10: R17.1 766.5,1190 815,1190 C31.2 865,1190 1009,1190 1226.46,972.54 U1.13@1226.46,944.91
NetC32_1: C32.1 R15.2 U4.2 | length 203.6
  Top Layer w10: R15.2@1269,1752.5 1269,1689 1332,1689 1356.2,1664.8 ; 1355.2,1663.8 U4.2
NetC32_2: C32.2 R18.2 U4.3 | length 195.9
  Top Layer w10: R18.2@1269,1555.5 1269,1611 1328,1611 1355.2,1638.2 U4.3
NetC33_1: C33.1 R16.2 U5.4 | length 190.4
  Top Layer w15: C33.1@891,1420 U5.4@1019.94,1420
  Top Layer w20: C33.1@880.65,1414.85 C33.1 878,1369 R16.2@884.5,1362.5
NetC33_2: C33.2 R20.2 U5.1 | length 195.6
  Top Layer w10: C33.2 C33.2@881.39,1490.89
  Top Layer w15: C33.2@890,1497 U5.1@1018.94,1497
  Top Layer w20: C33.2@881.39,1490.89 881.39,1538.87 879,1541.26 R20.2@883,1551.01
NetD3_1: D3.1 J3.2 R1.2 | length 318.1
  Top Layer w10: J3.2 509.31,236.69 636,236.69 716.2,236.69 R1.2 ; R1.2@756.25,275.25 R1.2@758.31,277.31
NetD5_1: D5.1 J3.1 R4.2 | length 316.7
  Top Layer w10: J3.1 523.31,463.31 636,463.31 706.2,463.31 R4.2
NetD6_1: D6.1 J4.2 R5.2 R8.2 RTHM.2 | length 397.1
  Top Layer w10: J4.2 486.31,586.69 D6.1 653.19,586.69 RTHM.2 R8.2 798.5,590 R5.2
NetD7_1: D7.1 J7.3 R10.1 R11.2 R12.1 | length 404.1
  Top Layer w20: J7.3 511.59,933.41 593.31,851.69 D7.1 684.31,851.69 R12.1@693.75,842.25 ; R10.1 695,766.5 R12.1@695,841 ; R12.1 R12.1@695,841 ; R11.2@758.5,841 R12.1@695,841
NetD9_1: D9.1 J8.1 J9.2 R16.1 | length 284.3
  Top Layer w20: J8.1 803.5,1365 R16.1
  Top Layer w50: J9.2@451,1380 639.74,1380
NetFB1_1: FB1.1 J1.6 | length 93.5
  Top Layer w25: FB1.1 J1.6
NetJ4_1: J4.1 R8.1 R9.2 R10.2 RTHM.1 | length 483
  Top Layer w10: J4.1 496,765 625,765 695,695 RTHM.1 R8.1 ; R10.2 760,761.5 R8.1 ; R9.2 778.5,710 R8.1
NetJ8_2: J8.2 R19.2
NetR7_1: R7.1 U4.5 U4.6 | length 1134.9
  Top Layer w10: R7.1@1190,1262 1190,1320 1508.2,1638.2 U4.6 ; R7.1@1190,1267.5 1232.5,1267.5 1249,1284 1249,1334 1350,1435 1415,1435 1558,1578 U4.5@1558,1612.61 ; U4.5@1552.41,1612.61 U4.5
NetR18_1: R18.1 U5.7 | length 100.3
  Top Layer w10: U5.7 R18.1@1271,1470.8
REFN1: C24.2 R13.1 U1.8 | length 653.7
  Top Layer w10: R13.1 827.5,959 881,959 C24.2 930,960 1030,960 1121,869 1346.2,869 1354.41,877.2 U1.8 U1.8@1357.2,940
REFP1: C24.1 R11.1 U1.7 | length 653.3
  Top Layer w10: R11.1 R11.1@830,845 ; R11.1@841.5,840 880,840 C24.1 931,839 972,839 973,840 1367.2,840 1380,852.8 U1.7
SCLK_AI: U1.28 U6.14 | length 448.9
  Top Layer w10: U1.28 1577.2,712.8 v1(1580,710) ; v1(1580,570) 1641,570 1661,590 U6.14@1806,590 ; U6.14@1795.87,589 U6.14@1822.87,589
  Mid-Layer 1 w10: v1(1580,570) v1(1580,710)
SCLK_DIG: J1.7 J5.2 U6.3 | length 816.1
  Top Layer w10: U6.3@2183.13,591 2286,591 2438,743 J5.2 ; v1(2840,740) J1.7
  Mid-Layer 2 w10: J5.2@2461,741 v1@2839,741
  Bottom Layer w10: J5.2 J5.2@2461,741 ; v1@2839,741 v1(2840,740)
SDI_AI: U1.27 U6.12 | length 381
  Top Layer w10: U1.27@1509,703 1509,661 1521,649 1589,649 1630,690 U6.12@1826,690
SDO_AI: U1.26 U6.11 | length 408.6
  Top Layer w10: U1.26 1482.36,751.36 1506,775 1579,775 1619,735 1716,735 U6.11@1826,735
START: U1.23 U7.6 | length 670.7
  Top Layer w10: U1.23 1405.59,575.41 1701,280 U7.6@1816.51,280
START_DIG: J1.2 J6.2 R21.1 U7.3 | length 1089.3
  Top Layer w10: U7.3@2011,280 v1@2370,280 ; J6.2@2450,200 2492,200 2782,490 J1.2
  Mid-Layer 2 w10: v1(2370,283) J6.2@2458.5,194.5
VDUT: C7.1 C21.1 C27.1 FB1.2 R21.2 U6.1 U6.7 U7.1 | length 2078.7
  Top Layer w25: U7.1 v2@2326,175 ; U6.1@2154.13,486 2327,486 2406,565 2495,565 2570,640 2570,669 2691,790 C7.1 FB1.2 ; U6.7@2154.13,786 v2@2255,786 ; R21.2@2261,367.5 C21.1
  Mid-Layer 1 w25: v2@2277,771 2381,667 v2@2381,565 ; v2(2331,180) 2331,490 v2@2391,550
  Mid-Layer 2 w25: v2@2388,547 2379,547 2389,557 v2(2389,564)
  other v2: 2265,786
pads on no net: J1.1 J1.3 J6.4 U1.3 U2.3 U2.7 U3.1 U3.3 U3.7 U3.8 U5.2 U5.3

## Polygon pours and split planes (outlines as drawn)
GNDA on Top Layer "GNDA-Top" (solid, remove dead copper, pour order 12): 1835,0 1835,415 1875,455 1875,975 2090,1190 2405,1505 3000,1505 3000,2999 2999,3000 0,3000 0,0
DGND on Top Layer "DGND-Top" (solid, remove dead copper, pour order 16): 1975,0 1975,350 2080,455 2095,470 2095,940 2475,1320 3000,1320 3000,-1
DGND on Bottom Layer "DGND-Bot" (solid, remove dead copper, pour order 15): 1975,0 1975,350 2080,455 2095,470 2095,940 2475,1320 3000,1320 3000,-1
GNDA on Bottom Layer "GNDA-Bot" (solid, remove dead copper, pour order 11): 1835,0 1835,415 1875,455 1875,975 2090,1190 2405,1505 3000,1505 3000,2999 2999,3000 0,3000 0,0
GNDA on Mid-Layer 1 "GNDA-Mid1" (solid, remove dead copper, pour order 10): 1835,0 1835,415 1875,455 1875,975 2090,1190 2405,1505 3000,1505 3000,2999 2999,3000 0,3000 0,0
DGND on Mid-Layer 1 "DGND-Mid1" (solid, remove dead copper, pour order 14): 1975,0 1975,350 2080,455 2095,470 2095,940 2475,1320 3000,1320 3000,-1
GNDA on Mid-Layer 2 "GNDA-Mid2" (solid, remove dead copper, pour order 9): 1835,0 1835,415 1875,455 1875,975 2090,1190 2405,1505 3000,1505 3000,2999 2999,3000 0,3000 0,0
DGND on Mid-Layer 2 "DGND-Mid2" (solid, remove dead copper, pour order 13): 1975,0 1975,350 2080,455 2095,470 2095,940 2475,1320 3000,1320 3000,-1

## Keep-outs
Keep-Out Layer:
  lines w10: 3000,2999 3000,0 0,0 0,3000 3000,3000

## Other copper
Top Layer:
  region net NetJ8_2: 692,1403 701,1394 726,1394 798,1466 798,1560 692,1560
  region net +15VA: 1040,2640 1040,2020 1000,1980 900,1980 770,2110 770,2430 760,2430 680,2510 680,2640
  region net -15VA: 540,2510 460,2430 460,1980 620,1820 620,1740 480,1740 180,2040 180,2640 540,2640
  region net -15VA: 1137,1417 1137,1393 1120,1376 1120,1308.5 1099,1308 1083,1292 1083,1262 1099,1246 1129,1246 1152.5,1270.5 1152,1271 1152,1301 1151,1300 1155,1307 1186,1346 1186,1417
  region net +5VA: 1387.2,702 1387.2,610 1344.2,610 1344.2,650 1373.2,679 1373.2,702
  region net +15VA: 1143,1497 1143,1523 1114,1552 1114,1592 1094,1629 1088,1631 1162,1631 1192,1599 1192,1497
  region net +5VA: 1582.37,2448.81 1582.37,2431.81 1634.37,2431.81 1658.37,2407.81 1685.37,2407.81 1685.37,2446.81 1658.37,2446.81 1656.37,2448.81
  region net +15VA: 1409.29,2448.93 1276,2395 1281,2375 1439.19,2372.5 1458,2391.3 1458,2448.93
  region net +5VA: 1724,1932 1724,1915 1760,1915 1785,1890 1866,1900 1877,1939 1767,1939 1760,1932
  region net +2.5VA: 1559,1957 1559,1940 1524,1940 1498,1914 1473,1914 1473,2014 1486,2014 1515,1985 1515,1966 1524,1957
  region net GNDA: 1580,2509.19 1625,2509.19 1627,2511.19 1627,2592.19 1615,2604.19 1592,2604.19 1578,2590.19 1578,2511.19
  region net GNDA: 1702,2063 1692,2053 1693,1972 1699,1966 1751,1966 1758,1973 1758,2030 1725,2063
  region net NetC26_1: 1580,2018 1580,1966 1543,1966 1543,2018
  region net +5VA: 1574,1672 1598,1672 1618,1692 1659,1692 1659,1653 1601,1653 1599,1655 1574,1655
  region net NetD9_1: 408,1353.25 408,1416.8 440.88,1451 624,1451 688,1387 733,1387 745,1375 745,1340 726,1321 451,1321

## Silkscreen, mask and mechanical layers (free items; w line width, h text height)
Top Overlay:
  lines w8: 913,1407 940.86,1379.14 961,1359 961,1340
  lines w10: 700,590 700,560 720,540 ; 800,1065 810,1055 875,1055
  text "GND" at 640,2740 h50 r90
  text "-15V" at 480,2730 h50 r90
  text "+15V" at 780,2730 h50 r90
  text "TIPD164 Rev A - 2014" at 1975,2510 h50
  text "PLC Analog Input" at 2115,2430 h50
  text "Module" at 2315,2350 h50
  text "VOLT/" at 110,1560 h50 r270
  text "mAMP" at 34,1542 h50 r270
  text "V/I-" at 196,1519 h30
  text "V/I+" at 190,1357 h30
  text "RED" at 195,1190 h30
  text "3-WIRE" at 96,1168 h50 r270
  text "RTD" at 24,1115 h50 r270
  text "BLK" at 199,1038 h30
  text "DGND" at 2530,1030 h30
  text "MISO" at 2530,943 h30
  text "BLK" at 197,891 h30
  text "/CS" at 2520,840 h30
  text "CJC" at 20,740 h50 r270
  text "SCLK" at 2525,730 h30
  text "CJC-" at 167,720 h30
  text "TC" at 81,713 h50 r270
  text "MOSI" at 2525,630 h30
  text "CJC+" at 171,572 h30
  text "J/K/N/T" at 20,481 h50 r270
  text "DGND" at 2525,480 h30
  text "TC-" at 191,400 h30
  text "TC" at 83,368 h50 r270
  text "DRDY" at 2525,290 h30
  text "TC+" at 191,245 h30
  text "START" at 2525,180 h30
  text "DGND" at 2520,80 h30
Top Solder:
  lines w10: 0,0 0,3000 3000,3000 3000,0 0,0
Mechanical 1:
  lines w10: 4.91,-69.01 4.91,-49.01 ; 64.91,-79.01 4.91,-59.01 ; 64.91,-39.01 4.91,-59.01 ; 1224,-59.01 4.91,-59.01 ; 1785.83,-59.01 3004.91,-59.01 ; 2944.91,-79.01 3004.91,-59.01 ; 2944.91,-39.01 3004.91,-59.01 ; 3004.91,-69.01 3004.91,-49.01
  text "3000 (mil)" at 1234,-95 h60

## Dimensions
2951,3000 to 2881,0 on Mechanical 1
-6.04,2967 to 2993.96,3157 on Mechanical 1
